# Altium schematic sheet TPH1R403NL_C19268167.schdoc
size 127 x 101 mm
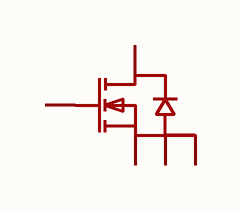
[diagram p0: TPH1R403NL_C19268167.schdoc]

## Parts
Q?  tph1r403nl_c19268167  [TDSON-8_L5.9-W5.2-P1.27-BL]  (value not drawn)

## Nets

Not connected (* = marked no-connect by the designer): Q? 1(S) 2(S) 3(S) 4(G) 5(D)

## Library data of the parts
Q? = tph1r403nl_c19268167: 数量:1个N沟道;漏源电压(Vdss):30V;连续漏极电流(Id):150A;导通电阻(RDS(on)):3.3mΩ@4.5V;耗散功率(Pd):75W;阈值电压(Vgs(th)):3V;; Manufacturer: TECH PUBLIC(台舟); AddInBom: yes; ModelId: ff3d8edf19694f3eb1c5df98919f3bc8; ModelTransform: 216.9287,242.5192,0,0,0,0,0,43.307,0; Number: 1个N沟道; Drain to Source Voltage: 30V; Current - Continuous Drain(Id): 150A; Pd - Power Dissipation: 75W; Gate Threshold Voltage (Vgs(th)): 3V; Gate Charge(Qg): 58nC@15V; Input Capacitance(Ciss): 5.93nF; Reverse Transfer Capacitance (Crss@Vds): 220pF; Type: N沟道; Output Capacitance(Coss): 660pF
